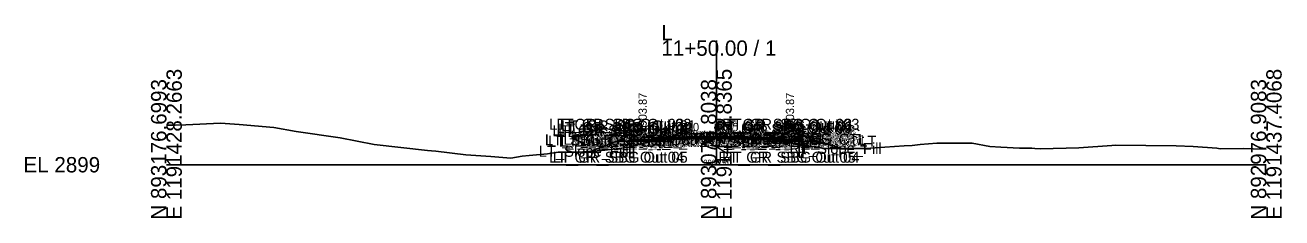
# Model space of a CAD drawing. Extents: x -26 to 203, y -10 to 7027.
# Drawn here: x -25.7 to 202.8, y 2990.3 to 3025.5 of the extents above; entities that cross this region are included whole.
import ezdxf

# ---------------------------------------------------------------- set-up
doc = ezdxf.new("R2010")
doc.units = 0
for name, color, linetype in [('Default', 7, 'Continuous'), ('Exist CMT Pavement', 7, 'Continuous'), ('Exist Cross Section Cell', 7, 'Continuous'), ('Exist XS Center Line Elevation Label', 7, 'Continuous'), ('Exist XS Ground Line', 7, 'Continuous'), ('Prop CMT Concrete Structures', 7, 'Continuous'), ('Prop CMT Guardrail Graphics', 7, 'Continuous'), ('Prop CMT Pvmt Course 1', 7, 'Continuous'), ('Prop CMT Pvmt Course 1 Wedge', 7, 'Continuous'), ('Prop CMT Pvmt Course 2', 7, 'Continuous'), ('Prop CMT Pvmt Course 2 Wedge', 7, 'Continuous'), ('Prop CMT Pvmt Course 3', 7, 'Continuous'), ('Prop CMT Pvmt Course 3 Wedge', 7, 'Continuous'), ('Prop CMT Pvmt Surface', 7, 'Continuous'), ('Prop CMT Pvmt Surface Shoulder', 7, 'Continuous'), ('Prop CMT Pvmt Wedge Surface 1', 7, 'Continuous'), ('Prop CMT Pvmt Wedge Surface 2', 7, 'Continuous'), ('Prop CMT Pvmt Wedge Surface 3', 7, 'Continuous'), ('Prop CMT Shld Paved Course 1', 7, 'Continuous'), ('Prop CMT Shld Paved Course 2', 7, 'Continuous'), ('Prop CMT Shld Paved Course 3', 7, 'Continuous'), ('Prop CMT Slope Grass', 7, 'Continuous'), ('Prop CMT Subgrade Earthwork', 7, 'Continuous'), ('Scratch_Level_6', 7, 'Continuous')]:
    doc.layers.add(name, color=color, linetype=linetype)

msp = doc.modelspace()

# ---------------------------------------------------------------- linework, layer by layer
at = {"layer": 'Exist CMT Pavement'}
for points in [[(89, 3004.77), (88.19, 3004.76)], [(88.19, 3004.76), (88.19, 3004.55)], [(88.19, 3004.55), (89, 3004.56)], [(89, 3004.56), (89, 3004.77)], [(100, 3004.91), (91.58, 3004.92)], [(91.58, 3004.92), (95.79, 3004.92)], [(95.79, 3004.92), (100, 3004.91)], [(104.31, 3004.85), (100, 3004.91)], [(100, 3004.91), (108.62, 3004.78)], [(108.62, 3004.78), (104.31, 3004.85)], [(111, 3004.77), (111.81, 3004.76)], [(111, 3004.56), (111, 3004.77)], [(111.81, 3004.55), (111, 3004.56)], [(111.81, 3004.76), (111.81, 3004.55)]]:
    msp.add_lwpolyline(points, dxfattribs=at)
at = {"layer": 'Exist Cross Section Cell'}
for p, q in [((100, 3000), (100, 3022.65)), ((0, 3000), (100, 3000)), ((100, 3000), (200, 3000))]:
    msp.add_line(p, q, dxfattribs=at)
at = {"layer": 'Exist XS Center Line Elevation Label'}
for points in [[(100, 3004.99), (91.58, 3004.82)], [(100, 3004.99), (108.62, 3004.82)]]:
    msp.add_lwpolyline(points, dxfattribs=at)
at = {"layer": 'Exist XS Ground Line'}
for points in [[(100, 3005.08), (91.58, 3004.91)], [(100, 3005.08), (108.62, 3004.9)]]:
    msp.add_lwpolyline(points, dxfattribs=at)
at = {"layer": 'Prop CMT Concrete Structures'}
for points in [[(100, 3005.2), (89, 3004.98)], [(100, 3005.2), (111, 3004.98)]]:
    msp.add_lwpolyline(points, dxfattribs=at)
at = {"layer": 'Prop CMT Pvmt Course 1'}
for points in [[(100, 3005.2), (89, 3004.98)], [(89, 3004.98), (89, 3004.77)], [(89, 3004.77), (91.58, 3004.82)], [(91.58, 3004.82), (89, 3004.77)], [(89, 3004.77), (89, 3004.56)], [(89, 3004.56), (91.58, 3004.62)], [(91.58, 3004.91), (100, 3005.08)], [(91.58, 3004.82), (91.58, 3004.91)], [(91.58, 3004.62), (91.58, 3004.82)], [(100, 3004.99), (100, 3005.2)], [(100, 3005.2), (111, 3004.98)], [(100, 3004.99), (100, 3005.2)], [(100, 3005.08), (100, 3004.99), (100, 3004.99)], [(108.62, 3004.9), (100, 3005.08)], [(100, 3005.08), (100, 3004.99), (100, 3004.99)], [(108.62, 3004.82), (108.62, 3004.9)], [(111, 3004.77), (108.62, 3004.82)], [(108.62, 3004.61), (108.62, 3004.82)], [(108.62, 3004.82), (111, 3004.77)], [(111, 3004.56), (108.62, 3004.61)], [(111, 3004.98), (111, 3004.77)], [(111, 3004.77), (111, 3004.56)]]:
    msp.add_lwpolyline(points, dxfattribs=at)
at = {"layer": 'Prop CMT Pvmt Course 1 Wedge'}
for points in [[(84.25, 3001.37), (84.25, 3007.37)], [(84.25, 3007.37), (85.58, 3007.37), (85.85, 3007.08)], [(85.85, 3006.5), (85.58, 3006.2), (84.91, 3006.2)], [(84.91, 3006.2), (84.91, 3001.37)], [(85.85, 3007.08), (85.58, 3006.79)], [(85.58, 3006.79), (85.85, 3006.5)], [(115.75, 3007.37), (114.42, 3007.37), (114.14, 3007.08)], [(114.14, 3007.08), (114.42, 3006.79)], [(114.42, 3006.79), (114.14, 3006.5)], [(114.14, 3006.5), (114.42, 3006.2), (115.08, 3006.2)], [(115.08, 3006.2), (115.08, 3001.37)], [(115.75, 3001.37), (115.75, 3007.37)], [(84.91, 3001.37), (84.25, 3001.37)], [(115.08, 3001.37), (115.75, 3001.37)]]:
    msp.add_lwpolyline(points, dxfattribs=at)
at = {"layer": 'Prop CMT Pvmt Course 2'}
for points in [[(100, 3004.78), (91.58, 3004.62)], [(100, 3004.78), (108.62, 3004.61)]]:
    msp.add_lwpolyline(points, dxfattribs=at)
at = {"layer": 'Prop CMT Pvmt Course 3'}
for points in [[(88.19, 3004.96), (85.85, 3004.87), (85.19, 3005.21)], [(111.81, 3004.96), (114.14, 3004.87), (114.81, 3005.21)], [(91.58, 3004.62), (89, 3004.56)], [(89, 3004.56), (89, 3004.23)], [(89, 3004.23), (91.58, 3004.28)], [(91.58, 3004.28), (91.58, 3004.62)], [(108.62, 3004.61), (111, 3004.56)], [(108.62, 3004.28), (108.62, 3004.61)], [(111, 3004.23), (108.62, 3004.28)], [(111, 3004.56), (111, 3004.23)]]:
    msp.add_lwpolyline(points, dxfattribs=at)
at = {"layer": 'Prop CMT Pvmt Course 3 Wedge'}
for p, q in [((3.54, 3007.27), (9.86, 3007.55)), ((9.86, 3007.55), (13.22, 3007.35)), ((0, 3007.24), (1.62, 3007.2)), ((1.62, 3007.2), (3.54, 3007.27)), ((13.22, 3007.35), (19.54, 3006.79)), ((19.54, 3006.79), (23.59, 3006.06)), ((23.59, 3006.06), (31.6, 3004.88)), ((31.6, 3004.88), (37.76, 3003.67)), ((37.76, 3003.67), (47.49, 3002.59)), ((79.17, 3002.57), (83.87, 3003.17)), ((83.87, 3003.17), (87.34, 3004.03)), ((87.34, 3004.03), (87.95, 3004.16)), ((87.95, 3004.16), (91.54, 3004.67)), ((91.54, 3004.67), (91.58, 3004.92)), ((91.58, 3004.92), (95.14, 3004.92)), ((95.14, 3004.92), (99.47, 3004.91)), ((99.47, 3004.91), (100, 3004.91)), ((100, 3004.91), (104.55, 3004.85)), ((104.55, 3004.85), (108.62, 3004.78)), ((108.62, 3004.78), (110.64, 3004.56)), ((110.64, 3004.56), (112, 3004.4)), ((112, 3004.4), (113.13, 3004.07)), ((113.13, 3004.07), (115.22, 3003.7)), ((115.22, 3003.7), (118.32, 3003.18)), ((118.32, 3003.18), (119.9, 3002.94)), ((119.9, 3002.94), (125.43, 3002.98)), ((125.43, 3002.98), (127.11, 3002.94)), ((127.11, 3002.94), (134.16, 3003.43)), ((134.16, 3003.43), (135.63, 3003.53)), ((135.63, 3003.53), (137.09, 3003.7)), ((137.09, 3003.7), (140.07, 3003.9)), ((140.07, 3003.9), (144.67, 3003.93)), ((144.67, 3003.93), (146.5, 3003.94)), ((146.5, 3003.94), (149.73, 3003.32)), ((149.73, 3003.32), (151.73, 3003.18)), ((151.73, 3003.18), (155.12, 3003.02)), ((155.12, 3003.02), (157.35, 3002.99)), ((157.35, 3002.99), (157.92, 3002.96)), ((157.92, 3002.96), (158.97, 3002.88)), ((158.97, 3002.88), (165.92, 3003.05)), ((165.92, 3003.05), (171.93, 3003.49)), ((171.93, 3003.49), (172.61, 3003.55)), ((172.61, 3003.55), (183.62, 3003.43)), ((183.62, 3003.43), (186.74, 3003.31)), ((186.74, 3003.31), (191.01, 3003)), ((191.01, 3003), (191.61, 3002.92)), ((191.61, 3002.92), (195.93, 3002.96)), ((195.93, 3002.96), (197.61, 3002.9)), ((47.49, 3002.59), (48.21, 3002.51)), ((48.21, 3002.51), (48.97, 3002.46)), ((48.97, 3002.46), (54.47, 3001.78)), ((54.47, 3001.78), (58.99, 3001.5)), ((58.99, 3001.5), (62.63, 3001.22)), ((62.63, 3001.22), (64.67, 3001.57)), ((64.67, 3001.57), (65.98, 3001.69)), ((65.98, 3001.69), (69.3, 3001.99)), ((69.3, 3001.99), (71.26, 3002.28)), ((71.26, 3002.28), (74.87, 3002.32)), ((74.87, 3002.32), (79.17, 3002.57)), ((197.61, 3002.9), (200, 3002.84))]:
    msp.add_line(p, q, dxfattribs=at)
at = {"layer": 'Prop CMT Pvmt Surface'}
for points in [[(85.19, 3005.21), (84.41, 3005.61), (82.85, 3004.63), (77.19, 3002.45)], [(114.81, 3005.21), (115.58, 3005.61), (117.14, 3004.63), (122.81, 3002.96)]]:
    msp.add_lwpolyline(points, dxfattribs=at)
at = {"layer": 'Prop CMT Pvmt Surface Shoulder'}
for points in [[(89, 3004.98), (88.19, 3004.96)], [(111, 3004.98), (111.81, 3004.96)]]:
    msp.add_lwpolyline(points, dxfattribs=at)
at = {"layer": 'Prop CMT Pvmt Wedge Surface 1'}
for points in [[(88.19, 3004.96), (85.85, 3004.87), (85.19, 3005.21)], [(85.19, 3005.21), (85.19, 3004.55)], [(111.81, 3004.96), (114.14, 3004.87), (114.81, 3005.21)], [(114.81, 3005.21), (114.81, 3004.55)], [(85.19, 3004.55), (88.19, 3004.55)], [(88.19, 3004.55), (88.19, 3004.96)], [(111.81, 3004.55), (111.81, 3004.96)], [(114.81, 3004.55), (111.81, 3004.55)]]:
    msp.add_lwpolyline(points, dxfattribs=at)
at = {"layer": 'Prop CMT Pvmt Wedge Surface 2'}
for points in [[(88.19, 3004.55), (85.19, 3004.55), (84.69, 3004.55), (84.44, 3004.3)], [(84.44, 3004.3), (88.19, 3004.3)], [(88.19, 3004.3), (88.19, 3004.55)], [(111.81, 3004.55), (114.81, 3004.55), (115.31, 3004.55), (115.56, 3004.3)], [(111.81, 3004.3), (111.81, 3004.55)], [(115.56, 3004.3), (111.81, 3004.3)]]:
    msp.add_lwpolyline(points, dxfattribs=at)
at = {"layer": 'Prop CMT Shld Paved Course 1'}
for points in [[(89, 3004.98), (88.19, 3004.96)], [(88.19, 3004.96), (88.19, 3004.76)], [(88.19, 3004.76), (89, 3004.77)], [(89, 3004.77), (89, 3004.98)], [(89, 3004.77), (89, 3004.98)], [(91.58, 3004.82), (89, 3004.77)], [(100, 3005.08), (91.58, 3004.91)], [(91.58, 3004.91), (91.58, 3004.82)], [(100, 3005.08), (108.62, 3004.9)], [(108.62, 3004.9), (108.62, 3004.82)], [(108.62, 3004.82), (111, 3004.77)], [(111, 3004.98), (111.81, 3004.96)], [(111, 3004.77), (111, 3004.98)], [(111, 3004.77), (111, 3004.98)], [(111.81, 3004.76), (111, 3004.77)], [(111.81, 3004.96), (111.81, 3004.76)]]:
    msp.add_lwpolyline(points, dxfattribs=at)
at = {"layer": 'Prop CMT Shld Paved Course 2'}
for points in [[(100, 3004.99), (89, 3004.77)], [(89, 3004.77), (89, 3004.98)], [(100, 3004.99), (111, 3004.77)], [(111, 3004.77), (111, 3004.98)]]:
    msp.add_lwpolyline(points, dxfattribs=at)
at = {"layer": 'Prop CMT Shld Paved Course 3'}
for points in [[(89, 3004.56), (89, 3004.98)], [(100, 3004.78), (89, 3004.56)], [(100, 3004.78), (111, 3004.56)], [(111, 3004.56), (111, 3004.98)]]:
    msp.add_lwpolyline(points, dxfattribs=at)
at = {"layer": 'Prop CMT Slope Grass'}
for points in [[(89, 3004.56), (88.19, 3004.55)], [(88.19, 3004.55), (88.19, 3004.21)], [(88.19, 3004.21), (89, 3004.23)], [(89, 3004.23), (89, 3004.56)], [(111, 3004.56), (111.81, 3004.55)], [(111, 3004.23), (111, 3004.56)], [(111.81, 3004.21), (111, 3004.23)], [(111.81, 3004.55), (111.81, 3004.21)]]:
    msp.add_lwpolyline(points, dxfattribs=at)
at = {"layer": 'Prop CMT Subgrade Earthwork'}
for points in [[(88.19, 3004.3), (84.44, 3004.3), (81.99, 3004.3)], [(88.19, 3004.21), (88.19, 3004.3)], [(89, 3004.23), (88.19, 3004.21)], [(91.58, 3004.28), (89, 3004.23)], [(91.58, 3004.28), (91.6, 3004.92)], [(108.62, 3004.28), (108.61, 3004.78)], [(108.62, 3004.28), (111, 3004.23)], [(111, 3004.23), (111.81, 3004.21)], [(111.81, 3004.21), (111.81, 3004.3)], [(111.81, 3004.3), (115.56, 3004.3), (118.27, 3004.3)]]:
    msp.add_lwpolyline(points, dxfattribs=at)

# ---------------------------------------------------------------- texts
at = {"layer": 'Default'}
msp.add_text('-', height=0.0001, dxfattribs=at).set_placement((0, 3000))
at = {"layer": 'Exist Cross Section Cell'}
for s, p in [('L', (90, 3022.65)), ('11+50.00 / 1', (90, 3019.85)), ('EL 2899', (-26, 2998.6))]:
    msp.add_text(s, height=2.8, dxfattribs=at).set_placement(p)
for s, p in [('E 1191428.2663', (2.8, 2990)), ('E 1191432.8365', (102.8, 2990)), ('E 1191437.4068', (202.8, 2990)), ('N 893176.6993', (0, 2990)), ('N 893076.8038', (100, 2990)), ('N 892976.9083', (200, 2990))]:
    msp.add_text(s, height=2.8, rotation=90, dxfattribs=at).set_placement(p)
at = {"layer": 'Prop CMT Guardrail Graphics'}
for p in [(87.35, 3005.87), (114.14, 3005.87)]:
    msp.add_text('2903.87', height=1.5, rotation=90, dxfattribs=at).set_placement(p)
at = {"layer": 'Prop CMT Pvmt Course 2 Wedge'}
for s, p in [('LT_GR_SBG Out 03', (69.6, 3006.37)), ('LT_GR_SBG Out 02', (70.94, 3006.37)), ('LT_GR_SBG Out 09', (70.94, 3005.79)), ('LT_GR_SBG Out 08', (71.21, 3005.5)), ('LT_GR_SBG Out 01', (71.77, 3006.08)), ('RT_GR_SBG Out 08', (99.45, 3005.5)), ('RT_GR_SBG Out 02', (99.72, 3006.37)), ('RT_GR_SBG Out 09', (99.72, 3005.79)), ('RT_GR_SBG Out 01', (100.02, 3006.08)), ('RT_GR_SBG Out 03', (101.06, 3006.37)), ('LT_SBG_C1 Shelf Out', (68.83, 3003.55)), ('LT_Sub_OSS_DLT', (69.39, 3003.3)), ('LT_GR_SBG Out 06', (70.22, 3005.2)), ('LT_GR_SBG Out 07', (70.94, 3005.2)), ('LT_Sub_SBG Out', (71.62, 3003.3)), ('LT_GS_OS_CTL', (72.22, 3003.63)), ('LT_CG_Top_BOC', (73.47, 3004.21)), ('LT_CG_Bot_BOC', (73.5, 3003.55)), ('LT_GS_OS_SBG', (73.77, 3004.61)), ('LT_CG_Top_Gut', (74.09, 3003.87)), ('LT_Sub_OEOP_SBG', (74.64, 3003.3)), ('LT_PV_Sub_Tie_Out', (76.54, 3003.92)), ('LT_CG_Bot_IE', (78.1, 3003.55)), ('LT_Sub_OEOP', (78.3, 3003.21)), ('LT_PS2_OEOP', (78.42, 3003.76)), ('LT_PS3_OEOP', (78.42, 3003.55)), ('LT_PS1_OEOP', (78.99, 3003.96)), ('LT_Sub_OEOT', (79.08, 3003.23)), ('LT_PV_OEEOP_EG', (79.13, 3003.92)), ('LT_PV2_OEOT', (79.17, 3003.77)), ('LT_PV3_OEOT', (79.17, 3003.56)), ('LT_PV1_OEOT', (79.74, 3003.98)), ('LT_Sub_OEEOP', (80.8, 3003.28)), ('LT_PV2_OEEOP', (80.89, 3003.82)), ('LT_PV3_OEEOP', (80.89, 3003.62)), ('LT_PV1_OEEOP', (81.46, 3003.91)), ('LT_PV_EG_TestPt', (82.2, 3003.92)), ('RT_PV_IEEOP_EG', (88.14, 3003.91)), ('LT_PV_IEEOP_EG', (88.19, 3003.91)), ('RT_PV2_IEEOP', (89.91, 3003.99)), ('RT_PV3_IEEOP', (89.91, 3003.78)), ('LT_PV2_IEEOP', (89.95, 3003.99)), ('LT_PV3_IEEOP', (89.95, 3003.78)), ('RT_PV1_IEEOP', (90.47, 3004.08)), ('LT_PV1_IEEOP', (90.52, 3004.08)), ('RT_PV_EG_TestPt', (90.67, 3003.85)), ('RT_PV_Sub_Tie_Out', (93.5, 3003.78)), ('PV2_PGL', (93.91, 3003.99)), ('PV1_PGL', (94.47, 3004.2)), ('RT_PV_OEEOP_EG', (96.12, 3003.78)), ('RT_Sub_OEEOP', (97.79, 3003.28)), ('RT_PV2_OEEOP', (97.88, 3003.82)), ('RT_PV3_OEEOP', (97.88, 3003.61)), ('RT_Sub_OEOP_SBG', (98.22, 3003.3)), ('RT_PV1_OEEOP', (98.45, 3003.9)), ('RT_SBG_C1 Shelf Out', (99.41, 3003.55)), ('RT_GR_SBG Out 07', (99.72, 3005.2)), ('RT_GR_SBG Out 06', (100.34, 3005.2)), ('RT_Sub_OEOT', (101.03, 3003.23)), ('RT_PV2_OEOT', (101.13, 3003.77)), ('RT_PV3_OEOT', (101.13, 3003.56)), ('RT_CG_Bot_IE', (101.68, 3003.55)), ('RT_PV1_OEOT', (101.69, 3003.98)), ('RT_Sub_OEOP', (101.87, 3003.21)), ('RT_PS2_OEOP', (102, 3003.76)), ('RT_PS3_OEOP', (102, 3003.55)), ('RT_CG_Top_Gut', (102.33, 3003.87)), ('RT_PS1_OEOP', (102.57, 3003.96)), ('RT_Sub_SBG Out', (102.7, 3003.3)), ('RT_CG_Top_BOC', (103.05, 3004.21)), ('RT_CG_Bot_BOC', (103.08, 3003.55)), ('RT_GS_OS_SBG', (104.89, 3004.61)), ('RT_Sub_OSS_DLT', (105.63, 3003.3)), ('RT_GS_OS_CTL', (106.47, 3003.63)), ('LT_Slope_Fill', (67.71, 3001.45)), ('RT_Slope_Fill', (113.28, 3001.96)), ('LT_GR_SBG Out 04', (69.6, 3000.37)), ('LT_GR_SBG Out 05', (70.27, 3000.37)), ('RT_GR_SBG Out 05', (100.39, 3000.37)), ('RT_GR_SBG Out 04', (101.06, 3000.37))]:
    msp.add_text(s, height=2, dxfattribs=at).set_placement(p)
at = {"layer": 'Prop CMT Pvmt Surface Shoulder'}
for rotation, p in [(1.1458, (91.86, 3006.04)), (358.8542, (102.9, 3006.14))]:
    msp.add_text('0.020', height=1.5, rotation=rotation, dxfattribs=at).set_placement(p)
at = {"layer": 'Prop CMT Pvmt Wedge Surface 3'}
for s, rotation, p in [('2.60:1', 21.0305, (77.26, 3003.28)), ('3.39:1', 343.5557, (117.63, 3005.27))]:
    msp.add_text(s, height=1.5, rotation=rotation, dxfattribs=at).set_placement(p)
at = {"layer": 'Scratch_Level_6'}
msp.add_text('2903.91', height=1, dxfattribs=at).set_placement((97.66, 2999.91))

doc.saveas('drawing.dxf')
